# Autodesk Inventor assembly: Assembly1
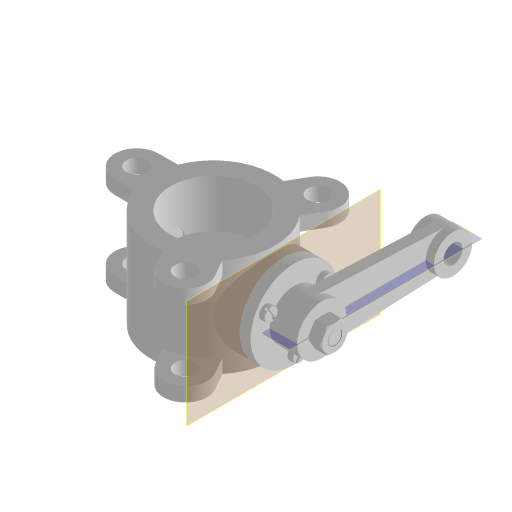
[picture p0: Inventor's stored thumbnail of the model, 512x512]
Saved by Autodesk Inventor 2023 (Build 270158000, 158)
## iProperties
Created: 2019-03
Part Number: Assembly1
Document SubType Name: Assembly
Designer: LENOVO-CADCIM
Author: LENOVO-CADCIM
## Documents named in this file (10)
- D:\PROJECTS\Project 2022\Autodesk Inventor For Professional 2023\RESOURCES INVENTOR 2023\RESOURCES INVENTOR 2023\Inventor_2023_tut\Inventor_2023_tut\c10_Inv_2023_tut\c10_Inv_tut_2023\c10_tut01_inv\Butterfly Valve\Butterfly Valve Assembly.iam
- D:\PROJECTS\Project 2022\Autodesk Inventor For Professional 2023\RESOURCES INVENTOR 2023\RESOURCES INVENTOR 2023\Inventor_2023_tut\Inventor_2023_tut\c10_Inv_2023_tut\c10_Inv_tut_2023\c10_tut01_inv\Butterfly Valve\Body.ipt
- D:\PROJECTS\Project 2022\Autodesk Inventor For Professional 2023\RESOURCES INVENTOR 2023\RESOURCES INVENTOR 2023\Inventor_2023_tut\Inventor_2023_tut\c10_Inv_2023_tut\c10_Inv_tut_2023\c10_tut01_inv\Butterfly Valve\Shaft.ipt
- D:\PROJECTS\Project 2022\Autodesk Inventor For Professional 2023\RESOURCES INVENTOR 2023\RESOURCES INVENTOR 2023\Inventor_2023_tut\Inventor_2023_tut\c10_Inv_2023_tut\c10_Inv_tut_2023\c10_tut01_inv\Butterfly Valve\Retainer.ipt
- D:\PROJECTS\Project 2022\Autodesk Inventor For Professional 2023\RESOURCES INVENTOR 2023\RESOURCES INVENTOR 2023\Inventor_2023_tut\Inventor_2023_tut\c10_Inv_2023_tut\c10_Inv_tut_2023\c10_tut01_inv\Butterfly Valve\Arm1.ipt
- D:\PROJECTS\Project 2022\Autodesk Inventor For Professional 2023\RESOURCES INVENTOR 2023\RESOURCES INVENTOR 2023\Inventor_2023_tut\Inventor_2023_tut\c10_Inv_2023_tut\c10_Inv_tut_2023\c10_tut01_inv\Butterfly Valve\Plate.ipt
- D:\PROJECTS\Project 2022\Autodesk Inventor For Professional 2023\RESOURCES INVENTOR 2023\RESOURCES INVENTOR 2023\Inventor_2023_tut\Inventor_2023_tut\c10_Inv_2023_tut\c10_Inv_tut_2023\c10_tut01_inv\Butterfly Valve\scew1.ipt
- D:\PROJECTS\Project 2022\Autodesk Inventor For Professional 2023\RESOURCES INVENTOR 2023\RESOURCES INVENTOR 2023\Inventor_2023_tut\Inventor_2023_tut\c10_Inv_2023_tut\c10_Inv_tut_2023\c10_tut01_inv\Butterfly Valve\Screw.ipt
- D:\PROJECTS\Project 2022\Autodesk Inventor For Professional 2023\RESOURCES INVENTOR 2023\RESOURCES INVENTOR 2023\Inventor_2023_tut\Inventor_2023_tut\c10_Inv_2023_tut\c10_Inv_tut_2023\c10_tut01_inv\Butterfly Valve\Parallel key.ipt
- D:\PROJECTS\Project 2022\Autodesk Inventor For Professional 2023\RESOURCES INVENTOR 2023\RESOURCES INVENTOR 2023\Inventor_2023_tut\Inventor_2023_tut\c10_Inv_2023_tut\c10_Inv_tut_2023\c10_tut01_inv\Butterfly Valve\Nut.ipt
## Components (12 placed, 9 different names)
1. Body:1 — Insert:1, Insert:2, Mate:1, Angle:2, Angle:3, Angle:4
2. Shaft:1 — Insert:1, Angle:2, Angle:3, Insert:3, Insert:4, Mate:3, Insert:11
3. Retainer:1 — Insert:2, Mate:1, Insert:7, Insert:10
4. Arm1:1 — Insert:10, Mate:2, Flush:1
5. Plate:1 — Insert:3, Insert:4, Insert:5, Insert:6
6. scew1:1 — Insert:5
7. scew1:2 — Insert:6
8. Parallel key:1 — Mate:2, Mate:3, Flush:1
9. Nut:1 — Insert:11, Angle:4
10. Screw:1 — Insert:7
11. Screw:2
12. Screw:3
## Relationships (16: Insert 9, Mate 3, Angle 3, Flush 1)
- Insert:1: Body:1 ↔ Shaft:1
- Insert:2: Body:1 ↔ Retainer:1
- Mate:1: Body:1 ↔ Retainer:1
- Angle:2: Body:1 ↔ Shaft:1
- Angle:3: Body:1 ↔ Shaft:1
- Insert:3: Shaft:1 ↔ Plate:1
- Insert:4: Shaft:1 ↔ Plate:1
- Insert:5: Plate:1 ↔ scew1:1
- Insert:6: Plate:1 ↔ scew1:2
- Insert:7: Retainer:1 ↔ Screw:1
- Insert:10: Retainer:1 ↔ Arm1:1
- Mate:2: Arm1:1 ↔ Parallel key:1
- Mate:3: Shaft:1 ↔ Parallel key:1
- Flush:1: Arm1:1 ↔ Parallel key:1
- Insert:11: Shaft:1 ↔ Nut:1
- Angle:4: Body:1 ↔ Nut:1
